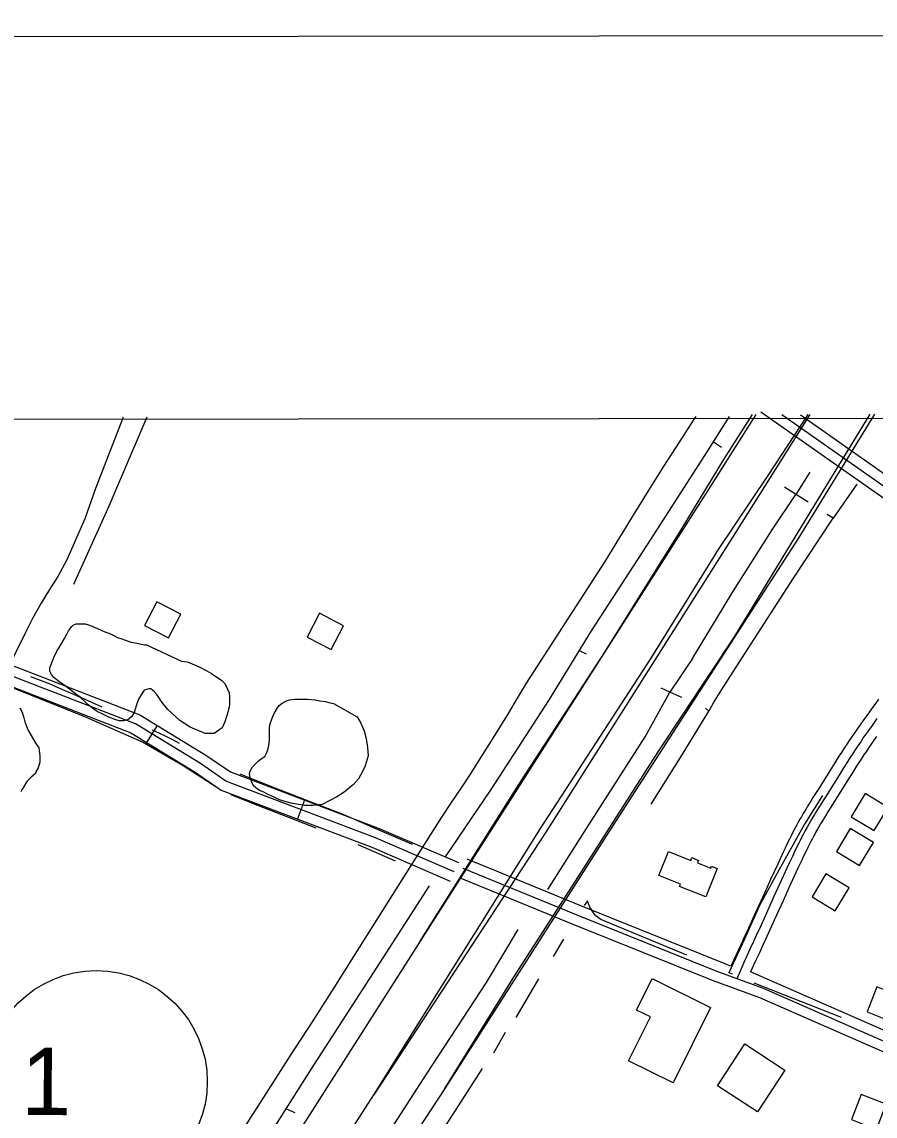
# Model space of a CAD drawing. Extents: x 3297735 to 3335592, y 670436 to 695807.
# Drawn here: x 3312597 to 3313866, y 692972 to 694598 of the extents above; entities that cross this region are included whole.
import ezdxf

# ---------------------------------------------------------------- set-up
doc = ezdxf.new("R2010")
doc.units = 0
for name, color, linetype in [('V-ANNO-SYMB', 7, 'Continuous'), ('V-BLDG-OTLN', 7, 'Continuous'), ('V-DTCH-CNTR', 7, 'Continuous'), ('V-GRID-FRAM', 7, 'Continuous'), ('V-RAIL-TRAK', 7, 'Continuous'), ('V-ROAD-CNTR', 7, 'Continuous'), ('V-ROAD-IDEN', 7, 'Continuous'), ('V-SITE-VEGE', 7, 'Continuous'), ('V-TOPO-SHOR', 7, 'Continuous')]:
    doc.layers.add(name, color=color, linetype=linetype)

msp = doc.modelspace()

# ---------------------------------------------------------------- linework, layer by layer
at = {"layer": 'V-ANNO-SYMB'}
msp.add_lwpolyline([(3301092, 671647.5), (3334175.2, 671681.1), (3334151.9, 694597.7), (3301068.7, 694564), (3301092, 671647.5)], dxfattribs=at)
at = {"layer": 'V-BLDG-OTLN'}
for points in [[(3312815.1, 693682.2), (3312833.6, 693717.7), (3312798.1, 693736.1), (3312779.7, 693700.6)], [(3313057, 693665), (3313075.4, 693700.5), (3313039.9, 693719), (3313021.5, 693683.5)], [(3313850.9, 693450.9), (3313830.2, 693416.7), (3313864.4, 693396), (3313885.1, 693430.2)], [(3313828.8, 693399), (3313808.1, 693364.8), (3313842.4, 693344.1), (3313863.1, 693378.3)], [(3313631, 693339.7), (3313614.2, 693297.5), (3313574.9, 693313.1), (3313576.2, 693316.5), (3313544.2, 693329.3), (3313558.4, 693364.9), (3313591.5, 693351.7), (3313593.1, 693355.9), (3313603.3, 693351.8), (3313601.8, 693348.1), (3313621.2, 693340.4), (3313622.3, 693343.2)], [(3313792.6, 693331.7), (3313771.9, 693297.5), (3313806.2, 693276.8), (3313826.9, 693311)], [(3313620.9, 693133.2), (3313565.4, 693021.1), (3313499.2, 693053.9), (3313531.5, 693119.2), (3313511.1, 693129.3), (3313534.2, 693176.1)], [(3313853.6, 693126.5), (3313890.8, 693111.9), (3313905.4, 693149.1), (3313868.2, 693163.7)], [(3313671.9, 693079.2), (3313731.6, 693040.2), (3313690.9, 692977.9), (3313631.2, 693016.8)], [(3313882.3, 692989.4), (3313845.1, 693003.9), (3313830.5, 692966.6), (3313867.8, 692952.1)]]:
    msp.add_lwpolyline(points, close=True, dxfattribs=at)
at = {"layer": 'V-DTCH-CNTR'}
msp.add_lwpolyline([(3312747.8, 694010.5), (3312706.8, 693904.1), (3312691, 693859.3), (3312664.3, 693798.2), (3312650.6, 693773.8), (3312638.3, 693754.1), (3312626, 693733.8), (3312613, 693711.4), (3312602.8, 693690.4), (3312573.9, 693631.7), (3312545.1, 693554.3), (3312481.3, 693402.3), (3312398.5, 693229.3), (3312309.4, 693032.6), (3312215.6, 692815.5), (3312147.7, 692661.4), (3312080.6, 692507.4), (3311991.5, 692287.5)], dxfattribs=at)
at = {"layer": 'V-GRID-FRAM'}
msp.add_lwpolyline([(3301851.4, 693996.5), (3333375, 694028.6), (3333401.5, 675844.1), (3301862, 675812)], close=True, dxfattribs=at)
at = {"layer": 'V-RAIL-TRAK'}
for points in [[(3313320.5, 693570.1), (3313334, 693592.6), (3313347.3, 693615.1), (3313464.3, 693796), (3313486, 693831.7), (3313507.9, 693867.2), (3313530, 693902.6), (3313552.2, 693937.9), (3313574.7, 693973.1), (3313597.3, 694008.1), (3313599.4, 694011.4)], [(3313182.9, 693354.9), (3313221.4, 693416), (3313236.1, 693437.7), (3313250.6, 693459.5), (3313264.9, 693481.4), (3313279.1, 693503.4), (3313293.1, 693525.6), (3313306.9, 693547.8), (3313320.5, 693570.1)], [(3312570.8, 692390.9), (3312600.3, 692438.3), (3312630, 692485.5), (3312659.9, 692532.6), (3312690, 692579.6), (3312719, 692624.3), (3312747.7, 692669.1), (3312776.2, 692714), (3312804.4, 692759.1), (3312832.4, 692804.3), (3312876.5, 692873.3), (3312920.4, 692942.4), (3312964.3, 693011.5), (3312996.8, 693061.7), (3313029.2, 693111.9), (3313061.3, 693162.3), (3313093.2, 693212.9), (3313182.9, 693354.9)]]:
    msp.add_lwpolyline(points, dxfattribs=at)
at = {"layer": 'V-ROAD-CNTR'}
for p, q in [((3312798.2, 693552.4), (3312782.6, 693526.8)), ((3313017.5, 693441.3), (3313006.9, 693413.3))]:
    msp.add_line(p, q, dxfattribs=at)
for points in [[(3311648.2, 694012.3), (3311771.5, 693955), (3312194.8, 693787.3), (3312546.9, 693623.3), (3312759.2, 693541.1), (3312854.6, 693483), (3312893.3, 693456.3), (3313117.3, 693371.5), (3313234.1, 693320.9)], [(3313240.1, 693334.7), (3313122.9, 693385.4), (3312900.3, 693469.7), (3312862.8, 693495.6), (3312765.9, 693554.6), (3312552.8, 693637.1), (3312200.8, 693801.1), (3311777.4, 693968.8), (3311683.7, 694012.4)], [(3311719.2, 694012.4), (3311783.3, 693982.6), (3312206.7, 693814.9), (3312558.6, 693650.9), (3312772.5, 693568.1), (3312870.9, 693508.2), (3312907.3, 693483.1), (3313128.6, 693399.3), (3313246.1, 693348.5)], [(3313768.8, 694014.5), (3313659, 693840.3), (3313376.2, 693393.9), (3313120.4, 693003.2)], [(3313120.6, 693003.5), (3313368.1, 693398.9), (3313532.5, 693652.1), (3313632.9, 693813.6), (3313706.6, 693923.9), (3313766, 694014.5)], [(3313688.4, 694014.4), (3313617.6, 693902.4), (3313189.2, 693231.9)], [(3313189.2, 693231.9), (3313335.9, 693464.6), (3313464, 693661.3), (3313577.3, 693843.1), (3313640.8, 693947.4), (3313683.6, 694014.4)], [(3313864.9, 694014.6), (3313751.1, 693830.2), (3313474.2, 693400.9), (3313225.9, 693012.8)], [(3313225.9, 693012.8), (3313327.8, 693176.5), (3313428.1, 693333.1), (3313543, 693513.2), (3313656.8, 693684.1), (3313769.2, 693868.8), (3313858.4, 694014.6)], [(3313695.6, 694018.3), (3313898.3, 693875.9), (3313911.4, 693852.5), (3313931.1, 693802.7), (3313947.8, 693757.2), (3313958.7, 693725.3), (3313967.1, 693710.5)], [(3313727.2, 694014.4), (3313909.7, 693886.2), (3313924.9, 693858.9), (3313945.1, 693808.1), (3313961.9, 693762.2), (3313972.5, 693731.5), (3313988.8, 693702.8), (3314005, 693676.3), (3314038.4, 693645.4), (3314081.2, 693621.7), (3314171.9, 693576.7), (3314383.1, 693497.3), (3314466.8, 693461.4), (3314769.4, 693343.7), (3314950.2, 693266.7), (3314964.1, 693261.9), (3314985.3, 693263.9), (3315000.4, 693275.9), (3315004.5, 693283.7), (3315009.2, 693302.5), (3315028.8, 693358.5), (3315072.3, 693461.6), (3315098.9, 693533.5)], [(3313754.5, 694013.6), (3313916.6, 693899.8)], [(3313870.8, 693591.1), (3313865.3, 693583.6), (3313860.5, 693577), (3313856.3, 693571.2), (3313848.9, 693561), (3313843.4, 693553.3), (3313839.4, 693547.5), (3313836.3, 693543.1), (3313831.8, 693536.6), (3313827.3, 693530), (3313824.6, 693526), (3313819.8, 693518.6), (3313815.5, 693512.1), (3313811.9, 693506.4), (3313805.6, 693496.5), (3313800.9, 693489), (3313786.9, 693466.6), (3313782, 693458.8), (3313773.3, 693445), (3313770, 693439.8), (3313767.2, 693435.2), (3313764.7, 693431.2), (3313762.5, 693427.6), (3313758.8, 693421.3), (3313756, 693416.6), (3313753.9, 693413), (3313750.9, 693407.6), (3313749.4, 693404.8), (3313747.9, 693402.1), (3313745.4, 693397.2), (3313743, 693392.6), (3313740.8, 693388.3), (3313738.8, 693384.2), (3313735, 693376.6), (3313731.8, 693370), (3313729, 693364.1), (3313724.3, 693353.9), (3313720.8, 693346.3), (3313710.3, 693323.4), (3313701.6, 693304.2), (3313688.5, 693275.4), (3313681.9, 693261), (3313675.3, 693246.6), (3313671.6, 693238.4), (3313665.9, 693226.1), (3313651.2, 693194.5)], [(3313868.4, 693562.4), (3313861.1, 693552.3), (3313855.7, 693544.6), (3313851.6, 693538.9), (3313848.6, 693534.6), (3313844.2, 693528.1), (3313839.7, 693521.6), (3313837.1, 693517.7), (3313832.3, 693510.4), (3313828.1, 693504), (3313824.5, 693498.4), (3313818.3, 693488.5), (3313813.6, 693481), (3313799.6, 693458.7), (3313794.7, 693450.8), (3313786, 693437), (3313782.8, 693431.9), (3313779.9, 693427.3), (3313777.5, 693423.4), (3313775.4, 693419.9), (3313771.7, 693413.7), (3313769, 693409.1), (3313767, 693405.6), (3313764.1, 693400.3), (3313762.6, 693397.7), (3313761.2, 693395), (3313758.7, 693390.2), (3313756.3, 693385.7), (3313754.2, 693381.5), (3313752.2, 693377.5), (3313748.5, 693370.1), (3313745.4, 693363.5), (3313742.6, 693357.7), (3313737.9, 693347.6), (3313734.4, 693340), (3313724, 693317.2), (3313715.2, 693298), (3313702.1, 693269.1), (3313695.6, 693254.7), (3313689, 693240.3), (3313685.2, 693232.1), (3313679.5, 693219.8), (3313673.8, 693207.5), (3313672, 693203.6), (3313670.5, 693200.1), (3313667.9, 693194.1), (3313664.1, 693184.9), (3313662.1, 693180.4), (3313660.1, 693175.8)], [(3313867.9, 693536), (3313863.9, 693530.3), (3313861, 693526), (3313856.5, 693519.6), (3313852.2, 693513.2), (3313849.6, 693509.4), (3313844.9, 693502.2), (3313840.7, 693495.8), (3313837.2, 693490.3), (3313830.9, 693480.5), (3313826.3, 693473.1), (3313812.3, 693450.7), (3313807.4, 693442.8), (3313798.7, 693429.1), (3313795.5, 693423.9), (3313792.7, 693419.4), (3313790.3, 693415.5), (3313788.2, 693412.1), (3313784.6, 693406.1), (3313782, 693401.6), (3313780.1, 693398.2), (3313777.2, 693393.1), (3313775.8, 693390.5), (3313774.4, 693388), (3313772, 693383.3), (3313769.7, 693378.9), (3313767.6, 693374.7), (3313765.6, 693370.9), (3313762, 693363.5), (3313758.9, 693357), (3313756.2, 693351.3), (3313751.5, 693341.3), (3313748, 693333.8), (3313737.6, 693311), (3313728.9, 693291.8), (3313715.8, 693262.9), (3313709.2, 693248.5), (3313702.6, 693234.1), (3313698.8, 693225.8), (3313693.1, 693213.5), (3313687.4, 693201.3), (3313680.6, 693186.1)], [(3316195.1, 692158), (3315869, 692288.8), (3315506.1, 692433.7), (3315318.1, 692504.1), (3315015.5, 692631), (3314723.7, 692747.9), (3314551, 692817.4), (3314462.7, 692856.2), (3314264.4, 692935.5), (3314179.8, 692969.1), (3313993.7, 693034.9), (3313899.6, 693073.9), (3313699.7, 693161.3), (3313629.3, 693187.1), (3313422.5, 693270.4), (3313253.4, 693339.7)], [(3313651.2, 693194.5), (3313428.1, 693284.2), (3313259.1, 693353.6)], [(3316189.5, 692144.1), (3315863.5, 692274.8), (3315500.7, 692419.7), (3315312.5, 692490.2), (3315009.8, 692617.1), (3314718.1, 692734), (3314545.2, 692803.6), (3314456.9, 692842.3), (3314258.9, 692921.6), (3314174.6, 692955.1), (3313988.4, 693020.9), (3313893.7, 693060.1), (3313694.1, 693147.4), (3313623.9, 693173.1), (3313416.8, 693256.5), (3313247.7, 693325.9)], [(3313189.2, 693231.9), (3312861.3, 692717), (3312518.5, 692178.8), (3312341.6, 691897.3), (3312242.3, 691742.4), (3312038.3, 691420.5), (3311841.3, 691109), (3311668.6, 690842.8), (3311504, 690585), (3311408.2, 690444.7), (3311309.2, 690278.1), (3311173.2, 690061.5), (3311058.2, 689890.8)], [(3313926, 693079.2), (3313905.5, 693087.7), (3313680.6, 693186.1)], [(3313225.9, 693012.8), (3312927.4, 692557.2), (3312688.4, 692164.2), (3312499.1, 691871), (3312353.9, 691636.1), (3312293.2, 691547), (3312159.4, 691339.8), (3312033.4, 691146.4), (3311880.5, 690903.5), (3311700.1, 690619.8), (3311629.8, 690502.5), (3311539.4, 690360.1), (3311438.5, 690202.4), (3311312.8, 690002.2), (3311226.4, 689864.9)], [(3312211.2, 691569.6), (3312305.1, 691726.5), (3312425.4, 691906), (3312517.7, 692057), (3312601.5, 692186.5), (3312684.8, 692313), (3312748.6, 692415.4), (3312814.9, 692521.5), (3312889.9, 692643.2), (3312978.4, 692789.2), (3313074.3, 692931.7), (3313120.6, 693003.5)]]:
    msp.add_lwpolyline(points, dxfattribs=at)
at = {"layer": 'V-ROAD-IDEN'}
msp.add_circle((3312707.9, 693022.9), 165, dxfattribs=at)
at = {"layer": 'V-SITE-VEGE'}
for points in [[(3312834.6, 693647.8), (3312843.5, 693646.8), (3312860.8, 693639.4), (3312872.1, 693633.4), (3312879, 693629.4), (3312885.5, 693624.9), (3312893.8, 693619.5), (3312898.8, 693614.5), (3312902.7, 693606.1), (3312905.6, 693600.6), (3312906.1, 693594.7), (3312906.1, 693582.8), (3312904.1, 693573.4), (3312899.1, 693557.6), (3312895.1, 693548.8), (3312883.2, 693540.4), (3312869.8, 693540.4), (3312847.6, 693549.9), (3312831.8, 693559.4), (3312814.1, 693576.2), (3312805.7, 693586.6), (3312797.9, 693598), (3312793.9, 693602.5), (3312789, 693606.5), (3312786, 693606.5), (3312779.1, 693604.5), (3312777.1, 693601.6), (3312770.6, 693591.2), (3312767.6, 693582.8), (3312764.1, 693571.5), (3312760.7, 693565.6), (3312754.7, 693560.6), (3312748.8, 693559.2), (3312742.3, 693559.2), (3312736.9, 693560.7), (3312726.5, 693564.7), (3312719.6, 693568.2), (3312709.3, 693573.1), (3312706.3, 693575.1), (3312697.9, 693581.6), (3312693, 693586.1), (3312684.1, 693594.5), (3312674.8, 693600.5), (3312661, 693611.4), (3312652.6, 693616.9), (3312644.2, 693623.8), (3312641.2, 693627.8), (3312638.8, 693632.7), (3312638.8, 693637.7), (3312642.3, 693647), (3312644.8, 693653), (3312649.8, 693663.8), (3312652.3, 693667.3), (3312660.7, 693681.6), (3312664.2, 693688), (3312666.7, 693692.9), (3312671.6, 693699.3), (3312673.6, 693701.3), (3312678.1, 693703.3), (3312691.4, 693703.2), (3312696.4, 693701.7), (3312705.3, 693698.2), (3312720.6, 693691.3), (3312726.5, 693689.3), (3312733.9, 693685.8), (3312739.3, 693682.8), (3312745.7, 693680.8), (3312755.1, 693677.3), (3312759.6, 693675.8), (3312768, 693674.3), (3312774.4, 693672.8), (3312779.8, 693671.8), (3312782.3, 693671.8)], [(3313095.8, 693564.9), (3313101.3, 693555.4), (3313106.2, 693544.5), (3313109.1, 693532.7), (3313111, 693519.3), (3313112, 693507), (3313107.5, 693492.1), (3313103.5, 693483.7), (3313097.5, 693472.9), (3313090.1, 693464.5), (3313076.2, 693453.2), (3313065.3, 693446.3), (3313043.5, 693435), (3313029.1, 693433.1), (3313017.3, 693433.1), (3312999.5, 693436.2), (3312990.1, 693438.7), (3312980.2, 693441.7), (3312972.3, 693445.7), (3312962.5, 693450.1), (3312957, 693453.1), (3312950.6, 693455.6), (3312947.2, 693458.1), (3312942.2, 693462.1), (3312940.3, 693465.5), (3312938.3, 693471), (3312936.8, 693474.5), (3312935.4, 693480.9), (3312936.4, 693484.3), (3312940.3, 693490.8), (3312943.3, 693494.2), (3312948.3, 693499.1), (3312950.8, 693501.1), (3312953.2, 693502.6), (3312955.7, 693504.5), (3312958.2, 693506), (3312960.7, 693510.9), (3312962.7, 693515.9), (3312964.2, 693522.3), (3312965.2, 693529.7), (3312965.3, 693547.5), (3312965.8, 693553.4), (3312969.3, 693563.3), (3312972.3, 693570.2), (3312977.2, 693578.6), (3312979.7, 693582.1), (3312984.2, 693585.5), (3312990.6, 693589), (3312995.1, 693590.4), (3313003, 693591.4), (3313021.8, 693591.3), (3313033.2, 693590.3), (3313040.1, 693588.8), (3313048.5, 693587.8), (3313053.4, 693586.3), (3313060.3, 693584.8)]]:
    msp.add_lwpolyline(points, close=True, dxfattribs=at)
msp.add_lwpolyline([(3312594.1, 693578.5), (3312597.5, 693572.1), (3312600, 693563.6), (3312601.4, 693557.7), (3312606.3, 693545.8), (3312618.1, 693525.5), (3312622.6, 693519.1), (3312624, 693507.2), (3312624, 693497.8), (3312621.5, 693489.4), (3312618, 693483.5), (3312617.5, 693481), (3312611, 693475.6), (3312604.6, 693469.2), (3312599.6, 693460.3), (3312597.6, 693457.4), (3312595.6, 693453.4)], dxfattribs=at)
at = {"layer": 'V-TOPO-SHOR'}
for p, q in [((3313637.4, 693965.5), (3313625.4, 693973.1)), ((3313768.6, 693928.8), (3313747.8, 693895.6)), ((3313436.4, 693658.2), (3313426, 693663)), ((3313594.1, 693651.9), (3313560.4, 693601.8)), ((3313152.9, 693350.4), (3313097.2, 693374.8)), ((3313438.3, 693291.5), (3313433.1, 693284.5)), ((3313402.5, 693234.8), (3313386.8, 693208.8)), ((3313653.8, 693182.5), (3313648.4, 693184.8)), ((3313365.1, 693175.8), (3313331.4, 693118.4)), ((3313815.6, 693118.5), (3313685.7, 693169.1)), ((3313315.8, 693095.8), (3313298.2, 693065.3)), ((3313003.6, 692976.5), (3312989.6, 692982.6))]:
    msp.add_line(p, q, dxfattribs=at)
for points in [[(3312674.6, 693762.2), (3312725.7, 693874.9), (3312783.3, 694010.6)], [(3313227.2, 693357.2), (3313294.8, 693457), (3313380.7, 693589.3), (3313444.2, 693692.8), (3313532.4, 693828.8), (3313617.2, 693960.1), (3313649.4, 694011.4)], [(3313838.5, 693911), (3313803.4, 693860.2), (3313794.6, 693865.8)], [(3313594.1, 693651.9), (3313654, 693750.9), (3313712.6, 693843), (3313747.8, 693895.6)], [(3313765.9, 693884.1), (3313734.1, 693904.3), (3313730.7, 693906.5)], [(3313618.6, 693573.6), (3313625.2, 693585.7), (3313638, 693605.6), (3313671.5, 693658.2), (3313744.4, 693770.9), (3313803.4, 693860.2)], [(3312609.9, 693625.1), (3312638.6, 693614.1), (3312657.6, 693605.8), (3312685.4, 693593.6), (3312715.9, 693579.8)], [(3312887.2, 693459.9), (3312836.8, 693492.4), (3312776.7, 693527.2), (3312693.3, 693563.9), (3312583.4, 693608.1)], [(3313378.9, 693308.7), (3313436.5, 693399.2), (3313523.9, 693535.2), (3313560.4, 693601.8)], [(3313578.1, 693593.8), (3313560.4, 693601.8), (3313547.7, 693607.6)], [(3313532.9, 693435.4), (3313578.8, 693508.4), (3313618.6, 693573.6), (3313613.3, 693577.8)], [(3312791.1, 693545.9), (3312809.3, 693537.3), (3312820, 693531.8), (3312831.1, 693525.7)], [(3313177.9, 693375.4), (3313119.2, 693400.5), (3313089.5, 693413.7), (3313072.3, 693420.9), (3313027.3, 693438.1), (3312973.8, 693459.2), (3312921.8, 693479.9)], [(3313034.5, 693399.5), (3312939.2, 693436.7), (3312908.4, 693449)], [(3313787.4, 693448.1), (3313760.9, 693405.5), (3313722.7, 693337.2), (3313693.9, 693284.6), (3313671.4, 693234.8), (3313648.4, 693184.8)], [(3313202.8, 693313.8), (3313129.6, 693200), (3313027.2, 693042.1), (3312989.6, 692982.6), (3312915.8, 692866), (3312838.3, 692741.4), (3312814.6, 692703.2), (3312687.1, 692502.3), (3312579.6, 692332), (3312559.7, 692300.6), (3312420, 692081.5), (3312414.8, 692073.4), (3312314.2, 691915), (3312304.9, 691901.8), (3312281.7, 691868.7)], [(3313585.6, 693211.1), (3313457.9, 693264), (3313450.5, 693269.6), (3313447.2, 693274), (3313441.6, 693282.3), (3313438.3, 693291.5)], [(3313334.7, 693248.9), (3313287.6, 693170.3), (3313199.1, 693035.4), (3313125.5, 692921.2)], [(3313281.4, 693042.7), (3313205.5, 692924.8), (3313181.2, 692885.2)]]:
    msp.add_lwpolyline(points, dxfattribs=at)

# ---------------------------------------------------------------- texts
at = {"layer": 'V-ROAD-IDEN'}
msp.add_text(' 1 ', height=100, rotation=359.688, dxfattribs=at).set_placement((3312558.8, 692973.7))

doc.saveas('drawing.dxf')
